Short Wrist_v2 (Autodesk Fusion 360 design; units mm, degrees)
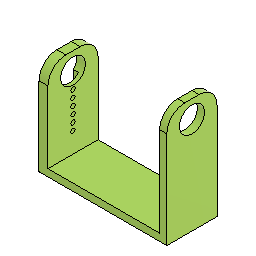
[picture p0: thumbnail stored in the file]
sketch "Sketch1" plane through (0, 0, 0) normal (0, 0, 1) x axis (1, 0, 0)
  line L1 (-17.85, -7) -> (17.85, -7)
  line L2 (-17.85, 7) -> (-17.85, -7)
  line L3 (17.85, 7) -> (-17.85, 7)
  line L4 (17.85, -7) -> (17.85, 7)
  line L5 (-17.85, 7) -> (17.85, -7)
  line L6 (17.85, 7) -> (-17.85, -7)
  line L7 (15.85, 7) -> (17.85, 7)
  line L8 (15.85, -7) -> (15.85, 7)
  line L9 (17.85, -7) -> (15.85, -7)
  line L10 (17.85, 7) -> (17.85, -7)
  line L11 (-15.35, 7) -> (-17.85, 7)
  line L12 (-15.35, -7) -> (-15.35, 7)
  line L13 (-17.85, -7) -> (-15.35, -7)
  line L14 (-17.85, 7) -> (-17.85, -7)
  point P6 (0, 0)
  point P1 (0, 0)
  point P4 (-17.85, 7)
  point P5 (17.85, 7)
  point P3 (-17.85, -7)
  point P7 (15.85, 7)
  point P10 (-15.35, 7)
  horizontal L1
  perpendicular L1 L2
  parallel L1 L3
  parallel L2 L4
  coincident L5 P6
  coincident L6 P6
  coincident P1 P6
  horizontal L7
  vertical L8
  horizontal L9
  vertical L10
  horizontal L11
  vertical L12
  horizontal L13
  vertical L14
  dimension "d1" distance P4 P5 = 35.7 (= "34 mm + 2 mm - 0.3 mm")
  dimension "d2" distance P3 P4 = 14
  dimension "d3" distance P5 P7 = 2
  dimension "d4" distance P4 P10 = 2.5
extrude "Extrude1" new body sketch "Sketch1" profile of L1 L3 L8 L12 along normal blind 2
extrude "Extrude2" add sketch "Sketch1" profile of L1 L3 L4 L7 L8 L9 L10 along normal blind 32 (= "2 mm + 30 mm")
sketch "Sketch2" plane through (17.85, 0, 0) normal (1, 0, 0) x axis (0, 1, 0)
  line L1 (7, 0) -> (-7, 0)
  line L2 (7, 32) -> (7, 0)
  line L3 (-7, 32) -> (7, 32)
  line L4 (-7, 0) -> (-7, 32)
  circle C1 centre (0, 27) radius 3.5
  point P6 (0, 27)
  dimension "d9" diameter C1 = 7
  dimension "d10" distance L3 P6 = 5 (= "( 7 / 2 ) * 1 mm + 1.5 mm")
extrude "Extrude3" cut sketch "Sketch2" profile of C1 against normal blind 2
extrude "Extrude4" add sketch "Sketch1" profile of L1 L2 L3 L11 L12 L13 L14 along normal blind 27 (= "2 mm + 25 mm")
fillet "Fillet1" radius 5
sketch "Sketch3" plane through (-17.85, 0, 0) normal (-1, 0, 0) x axis (0, -1, 0)
  line L1 (7, 0) -> (-7, 0)
  line L2 (7, 27) -> (7, 0)
  line L3 (-7, 27) -> (7, 27)
  line L4 (-7, 0) -> (-7, 27)
  line L5 (-1.997, 7.9409) -> (-2.65, 19.8909)
  line L6 (2.65, 19.8909) -> (1.997, 7.9409)
  line L7 (0, 27) -> (0, 0)
  line L8 (-7, 22.1) -> (7, 22.1)
  circle C1 centre (0, 13.65) radius 0.6
  circle C2 centre (0, 22.1) radius 2.3
  circle C3 centre (0, 9.65) radius 0.6
  arc A1 centre (0, 22.1) radius 3.45 clockwise from (-2.65, 19.8909) to (2.65, 19.8909)
  arc A2 centre (0, 8.05) radius 2 clockwise from (1.997, 7.9409) to (-1.997, 7.9409)
  circle C4 centre (0, 7.65) radius 0.6
  circle C5 centre (0, 11.65) radius 0.6
  circle C6 centre (0, 17.65) radius 0.6
  circle C7 centre (0, 15.65) radius 0.6
  circle C8 centre (0, 22.1) radius 3.45
  point P1 (0, 0)
  point P19 (0, 0)
  point P20 (0, 27)
  point P21 (7, 22.1)
  point P22 (-7, 22.1)
  coincident P1 P19
  midpoint L3 P20
  coincident L2 P21
  coincident L4 P22
  perpendicular L4 L8
  concentric C2 C8
  dimension "d19" distance L3 L8 = 4.9 (= "1.45 mm + ( 6.9 / 2 ) * 1 mm")
  dimension "d26" diameter C8 = 6.9
extrude "Extrude5" cut sketch "Sketch3" profile of L5 C1 L6 C3 A2 C4 C5 C6 C7 C8 against normal blind 1.4
extrude "Extrude8" cut sketch "Sketch3" profile of C1 C2 C3 A1 C4 C5 C6 C7 C8 against normal blind 2.5
fillet "Fillet2" radius 5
